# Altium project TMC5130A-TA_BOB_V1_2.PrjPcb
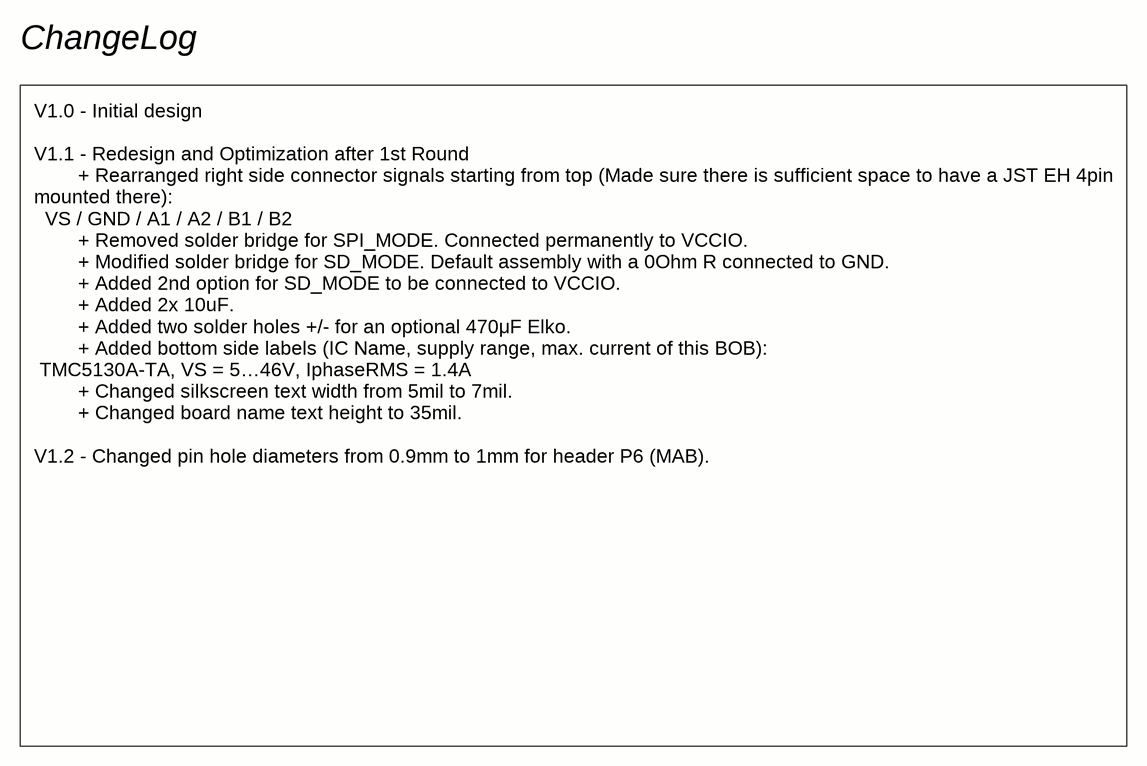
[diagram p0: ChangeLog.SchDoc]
BoardName: TMC5130A-TA_BOB; BoardVersion: 1.2; Chip: TMC5130A-TA; IRMS: 1.4A; VS: 5...46V
2 sheets, 27 parts. Net scope: global (net labels, ports and power ports of the same name join across sheets).
Board file: TMC5130A-TA_BOB_V1_2.PcbDoc
Sheets:
  ChangeLog.SchDoc
  TMC5130A-TA_BOB_V1_2.SchDoc

## Sheet ChangeLog.SchDoc
size A4

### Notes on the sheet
- ChangeLog
- V1.0 - Initial design
  V1.1 - Redesign and Optimization after 1st Round
  + Rearranged right side connector signals starting from top (Made sure there is sufficient space to have a JST EH 4pin mounted there):
  VS / GND / A1 / A2 / B1 / B2
  + Removed solder bridge for SPI_MODE. Connected permanently to VCCIO.
  + Modified solder bridge for SD_MODE. Default assembly with a 0Ohm R connected to GND.
  + Added 2nd option for SD_MODE to be connected to VCCIO.
  + Added 2x 10uF.
  + Added two solder holes +/- for an optional 470μF Elko.
  + Added bottom side labels (IC Name, supply range, max. current of this BOB):
  TMC5130A-TA, VS = 5…46V, IphaseRMS = 1.4A
  + Changed silkscreen text width from 5mil to 7mil.
  + Changed board name text height to 35mil.
  V1.2 - Changed pin hole diameters from 0.9mm to 1mm for header P6 (MAB).

## Sheet TMC5130A-TA_BOB_V1_2.SchDoc
size A4
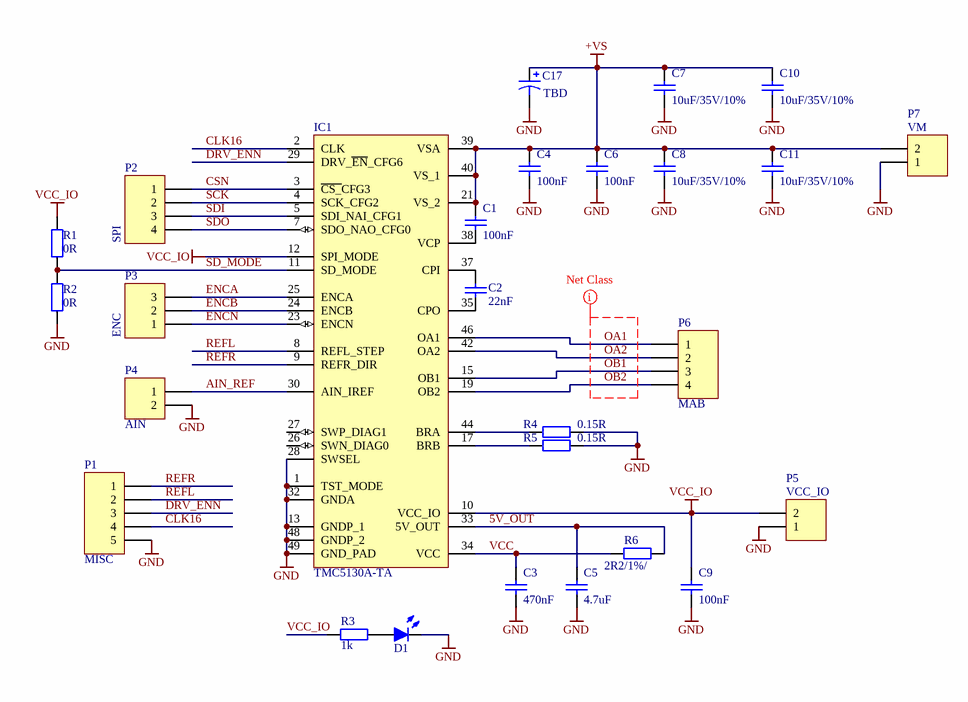
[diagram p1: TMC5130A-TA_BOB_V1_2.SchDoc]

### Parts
C1  100nF  [C0603]
C2  22nF  [C0603]
C3  470nF  [C0603]
C4  100nF  [C0603]
C5  4.7uF  [C0603]
C6  100nF  [C0603]
C7  10uF/35V/10%  [C1206]
C8  10uF/35V/10%  [C1206]
C9  100nF  [C0603]
C10  10uF/35V/10%  [C1206]
C11  10uF/35V/10%  [C1206]
C17  value TBD  [EXT_POL_CAP_2]  (hidden comment: Cap Pol1)
D1  LED, Blue, SMD, 20mA, 2.8V, 465 nm  [LED_0603]  (value not drawn)
IC1  TMC5130A-TA  [TMC5130_TQFP48-EP_0.5_7.0X7.0]
P1  MISC  [5_PIN_THT]
P2  SPI  [4_PIN_THT]
P3  ENC  [3_PIN_THT]
P4  AIN  [2_PIN_THT]
P5  VCC_IO  [2_PIN_THT]
P6  MAB  [4_PIN_THT_1mm_hole]
P7  VM  [2_PIN_THT]
R1  0R  [R0603]
R2  0R  [R0603]
R3  1k  [R0603]
R4  Resistance: 0.15R  [R1206]  (hidden comment: 0.15R / 0.5W / 1%)
R5  Resistance: 0.15R  [R1206]  (hidden comment: 0.15R / 0.5W / 1%)
R6  2R2/1%/  [R0603]

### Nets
+VS: C1.1 C4.1 C6.1 C7.2 C8.2 C10.2 C11.2 C17.1 IC1.21(VS_2) IC1.39(VSA) IC1.40(VS_1) P7.2
GND: C3.2 C4.2 C5.2 C6.2 C7.1 C8.1 C9.2 C10.1 C11.1 C17.2 D1.2(K) IC1.1(TST_MODE) IC1.13(GNDP_1) IC1.28(SWSEL) IC1.32(GNDA) IC1.48(GNDP_2) IC1.49(GND_PAD) P1.5 P4.2 P5.1 P7.1 R2.2 R4.1 R5.1
VCC_IO: C9.1 IC1.10(VCC_IO) IC1.12(SPI_MODE) P5.2 R1.1 R3.1
5V_OUT: C5.1 IC1.33(5V_OUT) R6.1
AIN_REF: IC1.30(AIN_IREF) P4.1
CLK16: IC1.2(CLK) P1.4
CSN: IC1.3(~{CS_}CFG3) P2.1
DRV_ENN: IC1.29(DRV_~{EN}_CFG6) P1.3
ENCA: IC1.25(ENCA) P3.3
ENCB: IC1.24(ENCB) P3.2
ENCN: IC1.23(ENCN) P3.1
OA1: IC1.46(OA1) P6.1
OA2: IC1.42(OA2) P6.2
OB1: IC1.15(OB1) P6.3
OB2: IC1.19(OB2) P6.4
REFL: IC1.8(REFL_STEP) P1.2
REFR: IC1.9(REFR_DIR) P1.1
SCK: IC1.4(SCK_CFG2) P2.2
SD_MODE: IC1.11(SD_MODE) R1.2 R2.1
SDI: IC1.5(SDI_NAI_CFG1) P2.3
SDO: IC1.7(SDO_NAO_CFG0) P2.4
VCC: C3.1 IC1.34(VCC) R6.2
NetC1_2: C1.2 IC1.38(VCP)
NetC2_1: C2.1 IC1.35(CPO)
NetC2_2: C2.2 IC1.37(CPI)
NetD1_1: D1.1(A) R3.2
NetIC1_17: IC1.17(BRB) R5.2
NetIC1_44: IC1.44(BRA) R4.2

Not connected (* = marked no-connect by the designer): IC1 26(SWN_DIAG0) 27(SWP_DIAG1)

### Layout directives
net class MotorPowerOut: OA1, OA2, OB1, OB2

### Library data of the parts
C1 = Capacitor: Ceramic capacitor; MPN: MC0603F104M500CT; Type: MLCC; Voltage rating: 50V; ComponentLinknDescription: Datasheet; MF: Multicomp; Precision: 20%
C2 = Capacitor: Ceramic capacitor; MPN: MC0603B223K500CT; Type: MLCC; Voltage rating: 50V; ComponentLinknDescription: Datasheet; MF: Multicomp; Precision: 20%
C3 = Capacitor: Ceramic capacitor; MPN: MC0603X474K160CT; Type: MLCC; Voltage rating: 16V; ComponentLinknDescription: Datasheet; MF: Multicomp; Precision: 10%
C4 C6 C9 = Capacitor: Ceramic capacitor; Manufacturer: Multicomp; MPN: MC0603F104M500CT; Type: MLCC; Voltage rating: 50V; ComponentLinknDescription: Datasheet; Precision: 20%
C5 = Capacitor: Ceramic capacitor; MPN: MC0603X475K100CT; Type: MLCC; Voltage rating: 10V; ComponentLinknDescription: Datasheet; MF: Multicomp; Precision: 10%
C7 C8 C10 C11 = Capacitor: Ceramic capacitor; MPN: GRM31CC8YA106KA12L; Type: MLCC; VoltageRating: 35V; ComponentLinknDescription: Datasheet; MF: MURATA; Capacitance: 10uF; Precision: 10%
C17 = Cap Pol1: Polarized Capacitor (Radial)
D1 = LED, Blue, SMD, 20mA, 2.8V, 465 nm: MPN: LTST-C191TBKT-5A; MF: Lite-On
IC1 = TMC5130A-TA: High voltage(up to 46V) controller for two-phase bipolar stepper motor, with SPI, Step/Dir, UART, TQFP48-EP(7x7); Manufacturer: TRINAMIC; Geometry.Height: 1,2mm; Ordercode - Distri#1: 1460-1124-ND
P1 = Header 5: Header, 5-Pin; Fitted: Not fitted
P2 = Header 4: Header, 4-Pin; Fitted: Not fitted
P3 = Header 3: Header, 3-Pin; Fitted: Not fitted
P4 P5 P7 = Header 2: Header, 2-Pin; Fitted: Not fitted
P6 = Wire-To-Board Connector, 2.5 mm, 4 Contacts, Header, EH Series, Through Hole, 1 Rows: MPN: B4B-EH-A; MF: JST (JAPAN SOLDERLESS TERMINALS); Fitted: Not fitted
R1 R2 = 0 ohm, 0603 [1608 Metric], 100 mW, MCWR Series: SMD Chip Resistor, Thick Film, 0 ohm, 0603 [1608 Metric], 100 mW, MCWR Series; MPN: MCWR06X000 PTL; Temp coefficient: *ppm; PowerRating: 100mW; MF: MULTICOMP
R3 = 1 kohm, 50 V, 0603 [1608 Metric], 63 mW, ± 1%, MC Series: MPN: MC0063W060311K; VoltageRating: 50V; Temp coefficient: *ppm; PowerRating: 63mW; MF: MULTICOMP
R4 R5 = 0.15 Ohm ±1% 0.5W, 1/2W Chip Resistor 1206 (3216 Metric) Automotive AEC-Q200, Current Sense Thick Film: MPN: ERJ-8BSFR15V; Temp coefficient: *ppm; MF: Panasonic
R6 = Resistor: MPN: MC0063W060312R2; Precision: 1%; Voltage rating: *V; Temp coefficient: *ppm; Power rating: *mW; ComponentLinknDescription: Datasheet; Resistance: 2R2; MF: Multicomp

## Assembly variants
ASM_TMC5130A-TA_BOB_V1_1: not fitted R1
